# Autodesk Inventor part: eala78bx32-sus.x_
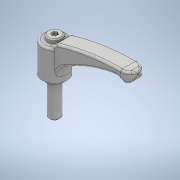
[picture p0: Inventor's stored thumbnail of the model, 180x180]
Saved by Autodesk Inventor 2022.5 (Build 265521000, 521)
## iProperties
Created: 2018-05
Part Number: eala78bx32-sus.x_
Material: 一般
Document SubType Name: Modeling
Designer: imaocorp
Density: 1 g/cm^3
Appearance: 既定
Sending System: SOLIDWORKS 2016-2016286
MC: AMD64
MC_MODEL: AMD64 Family 21 Model 2 Stepping 0, AuthenticAMD
OS: Windows_NT
FRU: Parasolid Version 28.0, build 224,  7-29-2016
FORMAT: text
GUISE: transmit
KEY: eala78bx32-sus
FILE: eala78bx32-sus.x_t
DATE: Fri May 18 11:32:04 2018
Author: imaocorp
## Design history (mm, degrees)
feature "Base1"
node "ソリッド1"
